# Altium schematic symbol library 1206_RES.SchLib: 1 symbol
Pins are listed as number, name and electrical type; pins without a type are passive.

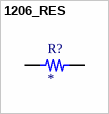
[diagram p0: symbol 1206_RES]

## 1206_RES
designator R?
1206 RESISTOR
footprint 1206
pins: 1, 2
